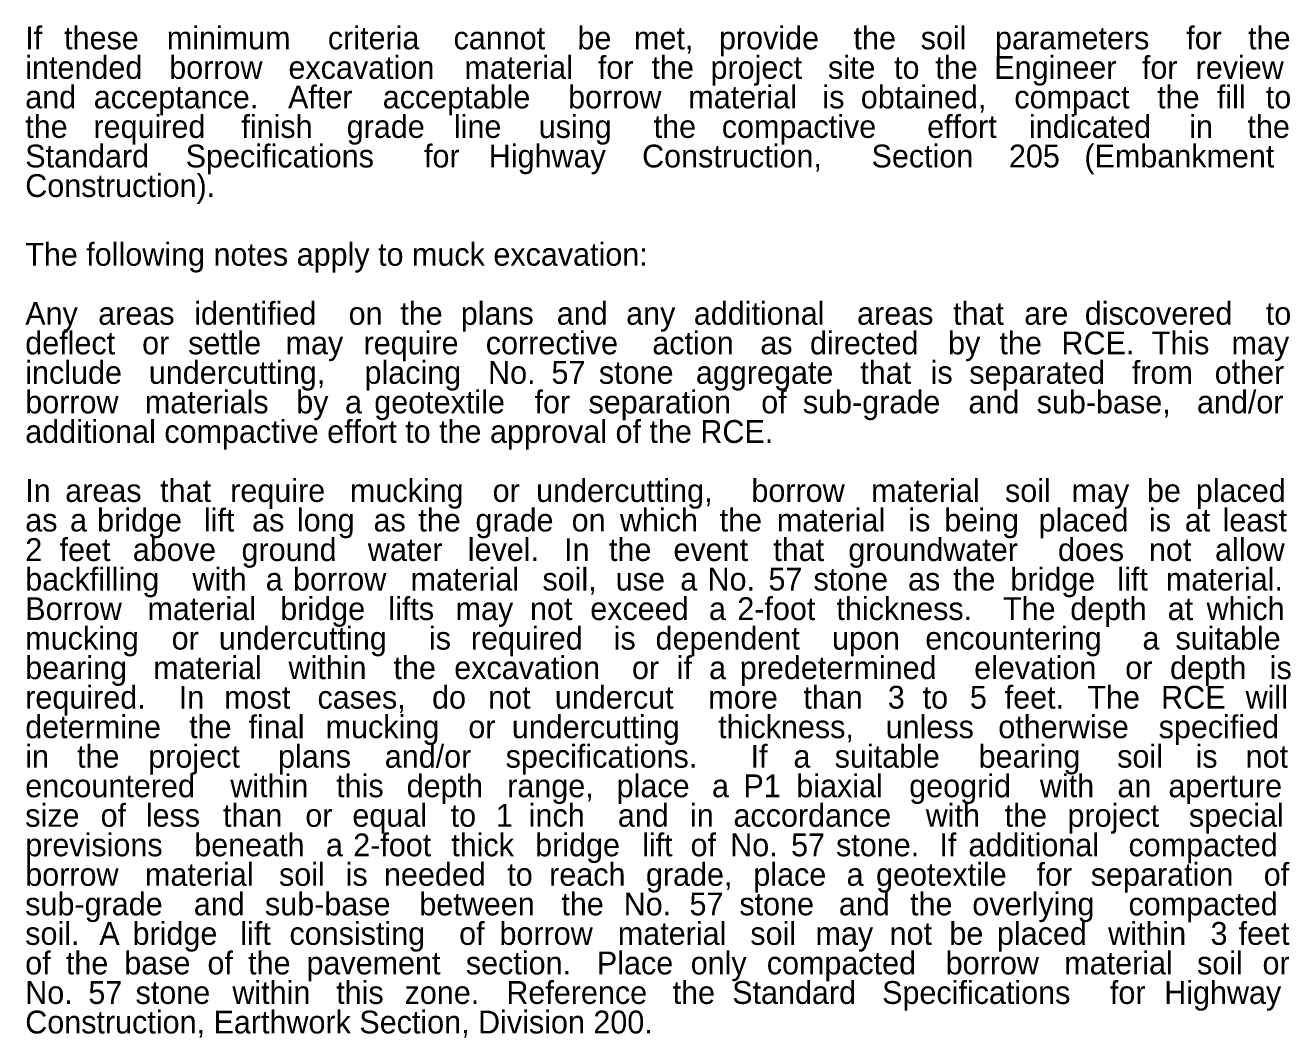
# Model space of a CAD drawing. Extents: x 4804 to 5434, y 4929 to 5221.
# Drawn here: x 5017.8 to 5094.6, y 5079.4 to 5140.9 of the extents above; entities that cross this region are included whole.
import ezdxf

# ---------------------------------------------------------------- set-up
doc = ezdxf.new("R2010")
doc.units = 0
doc.layers.add('RD_TX_RoadID', color=7, linetype='Continuous')

msp = doc.modelspace()

# ---------------------------------------------------------------- texts
at = {"layer": 'RD_TX_RoadID'}
for s, p in [('If ', (5017.804, 5139.42)), ('these ', (5020.162, 5139.42)), ('minimum ', (5026.39, 5139.42)), ('criteria ', (5036.165, 5139.42)), ('cannot ', (5043.791, 5139.42)), ('be ', (5051.308, 5139.42)), ('met, ', (5054.742, 5139.42)), ('provide ', (5059.895, 5139.42)), ('the ', (5068.058, 5139.42)), ('soil ', (5072.136, 5139.42)), ('parameters ', (5076.644, 5139.42)), ('for ', (5088.248, 5139.42)), ('the ', (5092.003, 5139.42)), ('intended ', (5017.804, 5137.629)), ('borrow ', (5026.541, 5137.629)), ('excavation ', (5033.775, 5137.629)), ('material ', (5044.45, 5137.629)), ('for ', (5052.545, 5137.629)), ('the ', (5055.802, 5137.629)), ('project ', (5059.381, 5137.629)), ('site ', (5066.508, 5137.629)), ('to ', (5070.518, 5137.629)), ('the ', (5073.022, 5137.629)), ('Engineer ', (5076.602, 5137.629)), ('for ', (5085.557, 5137.629)), ('review ', (5088.813, 5137.629)), ('and ', (5017.804, 5135.837)), ('acceptance. ', (5021.96, 5135.837)), ('After ', (5033.749, 5135.837)), (' acceptable ', (5038.978, 5135.837)), (' borrow ', (5050.229, 5135.837)), ('material ', (5058.038, 5135.837)), ('is ', (5066.172, 5135.837)), ('obtained, ', (5068.501, 5135.837)), ('compact ', (5077.815, 5135.837)), ('the ', (5086.485, 5135.837)), ('fill ', (5090.103, 5135.837)), ('to ', (5093.075, 5135.837)), ('the ', (5017.804, 5134.045)), ('required ', (5021.941, 5134.045)), ('finish ', (5030.916, 5134.045)), ('grade ', (5037.309, 5134.045)), ('line ', (5043.813, 5134.045)), ('using ', (5048.959, 5134.045)), ('the ', (5055.932, 5134.045)), ('compactive ', (5060.069, 5134.045)), ('effort ', (5072.525, 5134.045)), ('indicated ', (5078.702, 5134.045)), ('in ', (5088.428, 5134.045)), ('the ', (5091.962, 5134.045)), ('Standard ', (5017.804, 5132.253)), ('Specifications ', (5027.537, 5132.253)), ('for ', (5041.999, 5132.253)), ('Highway ', (5045.928, 5132.253)), ('Construction, ', (5055.232, 5132.253)), ('Section ', (5069.153, 5132.253)), ('205 ', (5077.489, 5132.253)), ('(Embankment ', (5082.066, 5132.253)), ('Construction).', (5017.804, 5130.461)), ('The following notes apply to muck excavation:', (5017.804, 5126.289)), ('Any ', (5017.804, 5122.705)), ('identified ', (5028.056, 5122.705)), ('the ', (5040.558, 5122.705)), ('plans ', (5044.231, 5122.705)), ('and ', (5050.054, 5122.705)), ('additional ', (5058.37, 5122.705)), ('that ', (5074.1, 5122.705)), ('discovered ', (5082.092, 5122.705)), ('areas ', (5022.23, 5122.705)), ('on ', (5037.423, 5122.705)), ('any ', (5054.265, 5122.705)), ('areas ', (5068.275, 5122.705)), ('are ', (5078.417, 5122.705)), ('to ', (5093.075, 5122.705)), ('deflect ', (5017.804, 5120.913)), ('or ', (5024.896, 5120.913)), ('settle ', (5027.69, 5120.913)), ('may ', (5033.6, 5120.913)), ('require ', (5038.33, 5120.913)), ('corrective ', (5045.746, 5120.913)), ('action ', (5055.85, 5120.913)), ('as ', (5062.405, 5120.913)), ('directed ', (5065.415, 5120.913)), ('by ', (5073.797, 5120.913)), ('the ', (5076.914, 5120.913)), ('RCE. ', (5080.675, 5120.913)), ('This ', (5086.156, 5120.913)), ('may ', (5090.992, 5120.913)), ('include ', (5017.804, 5119.122)), ('undercutting, ', (5025.303, 5119.122)), ('placing ', (5038.387, 5119.122)), ('No. ', (5045.886, 5119.122)), ('57 ', (5049.731, 5119.122)), ('stone ', (5052.61, 5119.122)), ('aggregate ', (5058.496, 5119.122)), ('that ', (5068.468, 5119.122)), ('is ', (5072.741, 5119.122)), ('separated ', (5075.082, 5119.122)), ('from ', (5084.946, 5119.122)), ('other ', (5089.973, 5119.122)), ('borrow ', (5017.804, 5117.33)), ('materials ', (5025.058, 5117.33)), ('by ', (5034.248, 5117.33)), ('geotextile ', (5038.979, 5117.33)), ('for ', (5048.704, 5117.33)), ('separation ', (5051.981, 5117.33)), ('of ', (5062.46, 5117.33)), ('sub-grade ', (5064.985, 5117.33)), ('and ', (5075.033, 5117.33)), ('sub-base, ', (5079.171, 5117.33)), ('and/or ', (5088.898, 5117.33)), ('a ', (5037.205, 5117.33)), ('additional compactive effort to the approval of the RCE. ', (5017.804, 5115.538)), ('In ', (5017.804, 5111.954)), ('that ', (5025.989, 5111.954)), ('require ', (5030.24, 5111.954)), ('mucking ', (5037.503, 5111.954)), ('undercutting, ', (5048.803, 5111.954)), ('borrow ', (5061.865, 5111.954)), ('material ', (5069.127, 5111.954)), ('soil ', (5077.25, 5111.954)), ('be ', (5085.864, 5111.954)), ('placed ', (5088.828, 5111.954)), ('areas ', (5020.229, 5111.954)), ('or ', (5046.162, 5111.954)), ('may ', (5081.287, 5111.954)), ('as ', (5017.804, 5110.162)), ('a ', (5020.521, 5110.162)), ('bridge ', (5022.164, 5110.162)), ('lift ', (5028.641, 5110.162)), ('as ', (5031.57, 5110.162)), ('long ', (5034.287, 5110.162)), ('as ', (5038.937, 5110.162)), ('the ', (5041.654, 5110.162)), ('grade ', (5045.122, 5110.162)), ('on ', (5050.956, 5110.162)), ('which ', (5053.886, 5110.162)), ('the ', (5059.934, 5110.162)), ('material ', (5063.402, 5110.162)), ('is ', (5071.385, 5110.162)), ('being ', (5073.565, 5110.162)), ('placed ', (5079.29, 5110.162)), ('is ', (5085.984, 5110.162)), ('at ', (5088.163, 5110.162)), ('least ', (5090.449, 5110.162)), ('2 ', (5017.804, 5108.371)), ('feet ', (5019.886, 5108.371)), ('above ', (5024.331, 5108.371)), ('ground ', (5030.927, 5108.371)), ('water ', (5038.596, 5108.371)), ('level. ', (5044.654, 5108.371)), ('In ', (5050.498, 5108.371)), ('the ', (5053.224, 5108.371)), ('event ', (5057.132, 5108.371)), ('that ', (5063.19, 5108.371)), ('groundwater ', (5067.742, 5108.371)), ('does ', (5080.462, 5108.371)), ('not ', (5085.983, 5108.371)), ('allow ', (5089.997, 5108.371)), ('backfilling ', (5017.804, 5106.579)), ('with ', (5027.948, 5106.579)), ('borrow ', (5034.051, 5106.579)), ('material ', (5041.187, 5106.579)), ('soil, ', (5049.184, 5106.579)), ('No. ', (5059.201, 5106.579)), ('57 ', (5062.898, 5106.579)), ('the ', (5074.098, 5106.579)), ('bridge ', (5077.579, 5106.579)), ('lift ', (5084.07, 5106.579)), ('material. ', (5087.012, 5106.579)), ('a ', (5032.396, 5106.579)), ('use ', (5053.633, 5106.579)), ('a ', (5057.545, 5106.579)), ('stone ', (5065.628, 5106.579)), ('as ', (5071.367, 5106.579)), ('Borrow ', (5017.804, 5104.787)), ('material ', (5025.219, 5104.787)), ('bridge ', (5033.28, 5104.787)), ('lifts ', (5039.835, 5104.787)), ('may ', (5043.917, 5104.787)), ('not ', (5048.432, 5104.787)), ('exceed ', (5052.084, 5104.787)), ('a ', (5059.288, 5104.787)), ('2-foot ', (5061.008, 5104.787)), ('thickness. ', (5067.022, 5104.787)), ('The ', (5077.125, 5104.787)), ('depth ', (5081.209, 5104.787)), ('at ', (5087.118, 5104.787)), ('which ', (5089.482, 5104.787)), ('mucking ', (5017.804, 5102.995)), ('undercutting ', (5029.55, 5102.995)), ('is ', (5042.298, 5102.995)), ('required ', (5044.839, 5102.995)), ('is ', (5053.506, 5102.995)), ('dependent ', (5056.048, 5102.995)), ('encountering ', (5072.413, 5102.995)), ('suitable ', (5087.596, 5102.995)), ('or ', (5026.686, 5102.995)), ('upon ', (5066.756, 5102.995)), ('a ', (5085.592, 5102.995)), ('bearing ', (5017.804, 5101.203)), ('material ', (5025.574, 5101.203)), ('within ', (5033.775, 5101.203)), ('the ', (5040.147, 5101.203)), ('excavation ', (5043.832, 5101.203)), ('if ', (5057.333, 5101.203)), ('predetermined ', (5061.158, 5101.203)), ('elevation ', (5075.378, 5101.203)), ('depth ', (5087.264, 5101.203)), ('is ', (5093.314, 5101.203)), ('or ', (5054.614, 5101.203)), ('a ', (5059.298, 5101.203)), ('or ', (5084.545, 5101.203)), ('required. ', (5017.804, 5099.411)), ('In ', (5027.118, 5099.411)), ('most ', (5029.876, 5099.411)), ('cases, ', (5035.536, 5099.411)), ('do ', (5042.488, 5099.411)), ('not ', (5045.891, 5099.411)), ('undercut ', (5049.937, 5099.411)), ('more ', (5059.25, 5099.411)), ('than ', (5065.018, 5099.411)), ('3 ', (5070.14, 5099.411)), ('to ', (5072.254, 5099.411)), ('5 ', (5075.118, 5099.411)), ('feet. ', (5077.233, 5099.411)), ('The ', (5082.247, 5099.411)), ('RCE ', (5086.724, 5099.411)), ('will ', (5091.848, 5099.411)), ('determine ', (5017.804, 5097.62)), ('the ', (5027.75, 5097.62)), ('final ', (5031.354, 5097.62)), ('mucking ', (5036.033, 5097.62)), ('undercutting ', (5047.327, 5097.62)), ('thickness, ', (5059.849, 5097.62)), ('unless ', (5070.011, 5097.62)), ('otherwise ', (5076.841, 5097.62)), ('specified ', (5086.572, 5097.62)), ('or ', (5044.689, 5097.62)), ('in ', (5017.804, 5095.828)), ('the ', (5020.947, 5095.828)), ('project ', (5025.272, 5095.828)), ('plans ', (5033.143, 5095.828)), ('and/or ', (5039.619, 5095.828)), ('specifications. ', (5046.953, 5095.828)), ('If ', (5061.811, 5095.828)), ('suitable ', (5066.915, 5095.828)), ('bearing ', (5075.646, 5095.828)), ('soil ', (5084.056, 5095.828)), ('is ', (5088.812, 5095.828)), ('a ', (5064.416, 5095.828)), ('not ', (5091.848, 5095.828)), ('encountered ', (5017.804, 5094.036)), ('within ', (5030.247, 5094.036)), ('this ', (5036.67, 5094.036)), ('depth ', (5040.945, 5094.036)), ('range, ', (5047.046, 5094.036)), ('place ', (5053.687, 5094.036)), ('a ', (5059.469, 5094.036)), ('P1 ', (5061.381, 5094.036)), ('biaxial ', (5064.583, 5094.036)), ('geogrid ', (5071.439, 5094.036)), ('with ', (5079.368, 5094.036)), ('an ', (5084.072, 5094.036)), ('aperture ', (5087.166, 5094.036)), ('size ', (5017.804, 5092.244)), ('of ', (5022.376, 5092.244)), ('less ', (5025.118, 5092.244)), ('than ', (5029.798, 5092.244)), ('equal ', (5037.649, 5092.244)), ('to ', (5043.617, 5092.244)), ('1 ', (5046.36, 5092.244)), ('inch ', (5048.352, 5092.244)), (' and ', (5053.245, 5092.244)), ('in ', (5058.138, 5092.244)), ('accordance ', (5060.774, 5092.244)), ('with ', (5072.44, 5092.244)), ('the ', (5077.225, 5092.244)), ('project ', (5081.042, 5092.244)), ('special ', (5088.407, 5092.244)), ('or ', (5034.798, 5092.244)), ('previsions ', (5017.804, 5090.452)), ('beneath ', (5028.056, 5090.452)), ('2-foot ', (5037.703, 5090.452)), ('thick ', (5043.652, 5090.452)), ('bridge ', (5048.743, 5090.452)), ('lift ', (5055.232, 5090.452)), ('of ', (5058.172, 5090.452)), ('No. ', (5060.576, 5090.452)), ('57 ', (5064.271, 5090.452)), ('If ', (5073.273, 5090.452)), ('additional ', (5075.032, 5090.452)), ('compacted ', (5084.744, 5090.452)), ('a ', (5036.049, 5090.452)), ('stone. ', (5067, 5090.452)), ('borrow ', (5017.804, 5088.66)), ('material ', (5025.072, 5088.66)), ('soil ', (5033.201, 5088.66)), ('is ', (5037.245, 5088.66)), ('needed ', (5039.569, 5088.66)), ('to ', (5047.054, 5088.66)), ('reach ', (5049.592, 5088.66)), ('grade, ', (5055.464, 5088.66)), ('place ', (5061.981, 5088.66)), ('a ', (5067.638, 5088.66)), ('geotextile ', (5069.426, 5088.66)), ('for ', (5079.166, 5088.66)), ('separation ', (5082.456, 5088.66)), ('of ', (5092.949, 5088.66)), ('sub-grade ', (5017.804, 5086.869)), ('and ', (5028.031, 5086.869)), ('sub-base ', (5032.349, 5086.869)), ('between ', (5041.717, 5086.869)), ('the ', (5050.334, 5086.869)), ('No. ', (5054.113, 5086.869)), ('57 ', (5058.107, 5086.869)), ('stone ', (5061.135, 5086.869)), ('and ', (5067.172, 5086.869)), ('the ', (5071.489, 5086.869)), ('overlying ', (5075.268, 5086.869)), ('compacted ', (5084.744, 5086.869)), ('soil. ', (5017.804, 5085.077)), ('A ', (5022.296, 5085.077)), ('bridge ', (5024.316, 5085.077)), ('lift ', (5030.85, 5085.077)), ('consisting ', (5033.835, 5085.077)), ('of ', (5044.13, 5085.077)), ('borrow ', (5046.579, 5085.077)), ('material ', (5053.758, 5085.077)), ('soil ', (5061.798, 5085.077)), ('be ', (5073.878, 5085.077)), ('placed ', (5076.759, 5085.077)), ('within ', (5083.509, 5085.077)), ('3 ', (5089.719, 5085.077)), ('feet ', (5091.418, 5085.077)), ('may ', (5065.753, 5085.077)), ('not ', (5070.247, 5085.077)), ('of ', (5017.804, 5083.285)), ('the ', (5020.27, 5083.285)), ('base ', (5023.812, 5083.285)), ('of ', (5028.86, 5083.285)), ('the ', (5031.327, 5083.285)), ('pavement ', (5034.868, 5083.285)), ('section. ', (5044.538, 5083.285)), ('Place ', (5052.486, 5083.285)), ('only ', (5058.18, 5083.285)), ('compacted ', (5062.797, 5083.285)), ('borrow ', (5073.649, 5083.285)), ('material ', (5080.845, 5083.285)), ('soil ', (5088.902, 5083.285)), ('or ', (5092.874, 5083.285)), ('No. ', (5017.804, 5081.493)), ('57 ', (5021.634, 5081.493)), ('stone ', (5024.498, 5081.493)), ('within ', (5030.37, 5081.493)), ('this ', (5036.67, 5081.493)), (' Reference ', (5046.479, 5081.493)), ('the ', (5057.081, 5081.493)), ('Standard ', (5060.696, 5081.493)), ('Specifications ', (5069.793, 5081.493)), ('for ', (5083.618, 5081.493)), ('Highway ', (5086.909, 5081.493)), ('zone. ', (5040.821, 5081.493)), ('Construction, Earthwork Section, Division 200. ', (5017.804, 5079.701))]:
    msp.add_text(s, height=1.3845, dxfattribs=at).set_placement(p)

doc.saveas('drawing.dxf')
